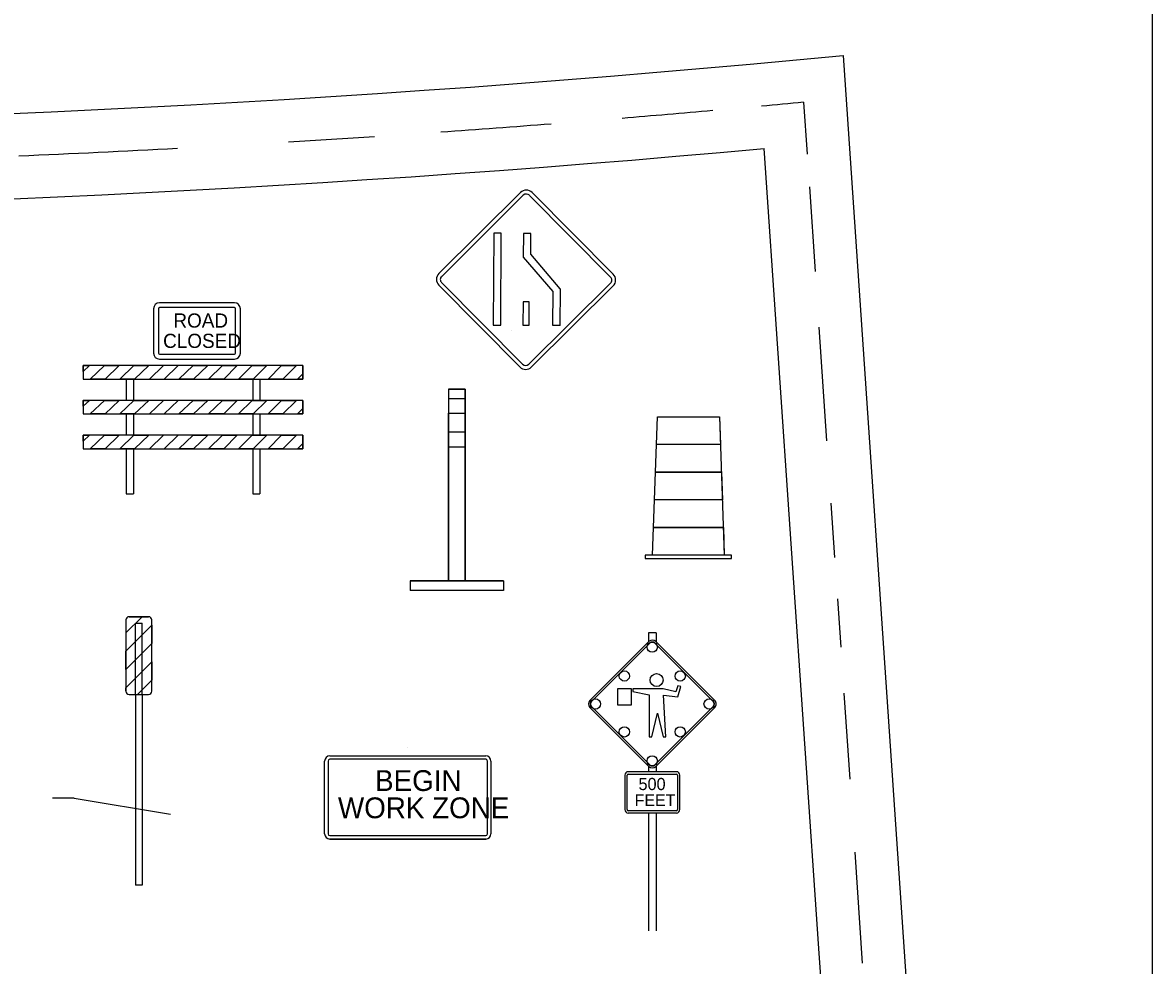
# Model space of a CAD drawing. Extents: x 49991.4 to 50021, y 49987.6 to 50011.4.
# Drawn here: x 50005.965 to 50008.615, y 50005.86 to 50008.071 of the extents above; entities that cross this region are included whole.
import ezdxf

# ---------------------------------------------------------------- set-up
doc = ezdxf.new("R2010")
doc.units = 0
for name, color, linetype in [('Level 1', 7, 'Continuous'), ('Level 2', 7, 'Continuous'), ('Level 25', 7, 'Continuous'), ('Level 4', 7, 'Continuous'), ('Level 7', 7, 'Continuous')]:
    doc.layers.add(name, color=color, linetype=linetype)

msp = doc.modelspace()

# ---------------------------------------------------------------- linework, layer by layer
at = {"layer": 'Level 1'}
for p, q in [((50007.8891, 50007.9941), (50008.1425, 50004.2775)), ((50007.7964, 50007.8845), (50007.8047, 50007.7625)), ((50007.7035, 50007.7757), (50007.8315, 50005.8993)), ((50007.8099, 50007.686), (50007.8234, 50007.4875)), ((50007.8323, 50007.3567), (50007.8505, 50007.0904)), ((50006.9633, 50007.2113), (50006.9633, 50006.7613)), ((50006.9633, 50007.2113), (50006.9633, 50006.7613)), ((50007.0027, 50007.2113), (50007.0027, 50006.7613)), ((50007.0027, 50006.7613), (50007.0027, 50007.2113)), ((50006.9633, 50006.7613), (50006.9633, 50007.1551)), ((50006.9633, 50007.0763), (50007.0027, 50007.0763)), ((50006.9633, 50006.7613), (50006.9633, 50007.0763)), ((50007.6015, 50007.0813), (50007.4511, 50007.0813)), ((50007.6015, 50007.0813), (50007.4511, 50007.0813)), ((50007.4466, 50006.9517), (50007.4488, 50007.0165)), ((50007.6037, 50007.0165), (50007.4488, 50007.0165)), ((50007.4488, 50007.0165), (50007.6037, 50007.0165)), ((50007.6037, 50007.0165), (50007.606, 50006.9517)), ((50007.606, 50006.9517), (50007.4466, 50006.9517)), ((50007.606, 50006.9517), (50007.4466, 50006.9517)), ((50007.8605, 50006.9435), (50007.8692, 50006.816)), ((50007.6083, 50006.8869), (50007.4443, 50006.8869)), ((50007.6083, 50006.8869), (50007.4482, 50006.8869)), ((50007.4482, 50006.8869), (50007.6083, 50006.8869)), ((50007.0927, 50006.7613), (50006.8733, 50006.7613)), ((50006.8733, 50006.7613), (50006.8733, 50006.7388)), ((50006.8733, 50006.7613), (50007.0927, 50006.7613)), ((50007.0927, 50006.7613), (50007.0927, 50006.7388)), ((50007.0927, 50006.7388), (50006.8733, 50006.7388)), ((50007.8758, 50006.7198), (50007.8835, 50006.6061)), ((50006.2448, 50006.6775), (50006.2068, 50006.6395)), ((50006.26, 50006.6775), (50006.2448, 50006.6775)), ((50007.4324, 50006.6398), (50007.4324, 50006.6183)), ((50007.4506, 50006.6398), (50007.4324, 50006.6398)), ((50007.4506, 50006.6398), (50007.4506, 50006.6183)), ((50007.4342, 50006.62), (50007.295, 50006.4809)), ((50007.4367, 50006.6162), (50007.2984, 50006.4777)), ((50007.5848, 50006.4777), (50007.4464, 50006.6162)), ((50007.5881, 50006.4809), (50007.4496, 50006.6193)), ((50007.3604, 50006.4701), (50007.3604, 50006.5088)), ((50007.3604, 50006.5088), (50007.392, 50006.5088)), ((50007.392, 50006.5088), (50007.392, 50006.4701)), ((50007.4668, 50006.5086), (50007.3956, 50006.5086)), ((50007.3956, 50006.5086), (50007.3956, 50006.5022)), ((50007.4967, 50006.5017), (50007.4668, 50006.5086)), ((50007.5011, 50006.5154), (50007.4967, 50006.5017)), ((50007.5086, 50006.5135), (50007.5011, 50006.5154)), ((50007.5017, 50006.4898), (50007.5086, 50006.5135)), ((50006.2291, 50006.4952), (50006.2291, 50006.2283)), ((50006.2453, 50006.4952), (50006.2453, 50006.2255)), ((50007.3956, 50006.5022), (50007.4342, 50006.4946)), ((50007.4342, 50006.4946), (50007.4342, 50006.396)), ((50007.4732, 50006.396), (50007.4681, 50006.4936)), ((50007.4681, 50006.4936), (50007.5017, 50006.4898)), ((50007.8909, 50006.4985), (50007.9046, 50006.2964)), ((50007.295, 50006.4648), (50007.4335, 50006.3264)), ((50007.2984, 50006.468), (50007.4367, 50006.3296)), ((50007.392, 50006.4701), (50007.3604, 50006.4701)), ((50007.4464, 50006.3296), (50007.5848, 50006.468)), ((50007.4496, 50006.3264), (50007.5881, 50006.4648)), ((50007.4405, 50006.396), (50007.4537, 50006.4515)), ((50007.4537, 50006.4515), (50007.4669, 50006.396)), ((50007.4342, 50006.396), (50007.4405, 50006.396)), ((50007.4669, 50006.396), (50007.4732, 50006.396)), ((50006.6851, 50006.3514), (50007.0509, 50006.3514)), ((50006.8681, 50006.3707), (50006.8681, 50006.3707)), ((50006.8681, 50006.3707), (50006.8681, 50006.3707)), ((50006.8681, 50006.3707), (50006.8681, 50006.3707)), ((50006.8681, 50006.3707), (50006.8681, 50006.3707)), ((50006.8681, 50006.3707), (50006.8681, 50006.3707)), ((50006.8681, 50006.3707), (50006.8681, 50006.3707)), ((50006.6728, 50006.1683), (50006.6728, 50006.3389)), ((50006.681, 50006.3389), (50006.681, 50006.1683)), ((50007.0509, 50006.3431), (50006.6851, 50006.3431)), ((50007.055, 50006.1683), (50007.055, 50006.3389)), ((50007.0631, 50006.3389), (50007.0631, 50006.1683)), ((50007.4324, 50006.3274), (50007.4324, 50006.3139)), ((50007.4506, 50006.3274), (50007.4506, 50006.3139)), ((50006.0853, 50006.2522), (50006.0345, 50006.2522)), ((50006.0853, 50006.2522), (50006.3116, 50006.2145)), ((50007.4324, 50006.2172), (50007.4324, 50005.9408)), ((50007.4506, 50006.2172), (50007.4506, 50005.9408)), ((50006.6851, 50006.1643), (50007.0509, 50006.1643)), ((50006.6851, 50006.1561), (50007.0509, 50006.1561)), ((50007.0509, 50006.1561), (50006.6851, 50006.1561)), ((50007.9163, 50006.1256), (50007.934, 50005.8651)), ((50007.8315, 50005.8993), (50007.9298, 50004.4565))]:
    msp.add_line(p, q, dxfattribs=at)
for points in [[(50008.6146, 50011.2628), (50000.3356, 50011.2628), (50000.3356, 50000.0624), (50008.6146, 50000.0624)], [(50007.6105, 50006.8221), (50007.442, 50006.8221), (50007.4534, 50007.1461), (50007.5992, 50007.1461)], [(50007.6083, 50006.8869), (50007.6105, 50006.8221), (50007.442, 50006.8221), (50007.4443, 50006.8869), (50007.6044, 50006.8869)], [(50007.425, 50006.814), (50007.6275, 50006.814), (50007.6275, 50006.8221), (50007.425, 50006.8221)]]:
    msp.add_lwpolyline(points, close=True, dxfattribs=at)
for points in [[(50007.4511, 50007.0813), (50007.4534, 50007.1461), (50007.5992, 50007.1461), (50007.6015, 50007.0813)], [(50006.2068, 50006.6699), (50006.2068, 50006.5028)], [(50006.2068, 50006.6699), (50006.2068, 50006.5028)], [(50006.2144, 50006.6775), (50006.26, 50006.6775)], [(50006.26, 50006.6775), (50006.2144, 50006.6775)], [(50006.2676, 50006.5028), (50006.2676, 50006.6699)], [(50007.501, 50006.5153), (50007.5011, 50006.5154)], [(50006.2144, 50006.4952), (50006.26, 50006.4952)], [(50007.5015, 50006.4899), (50007.5018, 50006.4902)], [(50007.3919, 50006.4701), (50007.392, 50006.4703)]]:
    msp.add_lwpolyline(points, dxfattribs=at)
for centre in [(50007.4415, 50006.6062), (50007.376, 50006.5384), (50007.5071, 50006.5384), (50007.3084, 50006.4728), (50007.5748, 50006.4728), (50007.376, 50006.4073), (50007.5071, 50006.4073), (50007.4415, 50006.3396)]:
    msp.add_circle(centre, 0.012, dxfattribs=at)
for centre, radius, start, end in [((50004.3941, 50043.9715), 36.1468, 264.4363, 275.54852), ((50004.3941, 50043.9715), 36.2468, 275.22979, 275.38583), ((50004.3941, 50043.9715), 36.2468, 274.71135, 275.04859), ((50004.3941, 50043.9715), 36.2468, 274.03687, 274.44663), ((50004.3941, 50043.9715), 36.2468, 273.47079, 273.79018), ((50004.3941, 50043.9715), 36.3468, 264.75129, 275.22467), ((50004.3941, 50043.9715), 36.2468, 272.4697, 273.05829), ((50006.2144, 50006.6699), 0.00759, 90, 180), ((50006.2144, 50006.6699), 0.00759, 90, 180), ((50006.26, 50006.6699), 0.00759, 0, 90), ((50006.2144, 50006.5028), 0.00759, 180, 270), ((50006.26, 50006.5028), 0.00759, 270, 360), ((50006.6852, 50006.339), 0.0123, 90, 180), ((50007.0509, 50006.339), 0.0123, 0, 90), ((50006.6852, 50006.339), 0.00406, 90, 180), ((50007.0509, 50006.339), 0.00406, 0, 90), ((50006.6852, 50006.1683), 0.0123, 180, 270), ((50006.6852, 50006.1683), 0.00406, 180, 270), ((50007.0509, 50006.1683), 0.0123, 270, 360), ((50007.0509, 50006.1683), 0.00406, 270, 360)]:
    msp.add_arc(centre, radius, start, end, dxfattribs=at)
for centre, major_axis, start_param, end_param in [((50007.4416, 50006.6113), (0, 0.0114), 5.497787, 6.983728), ((50007.4415, 50006.6113), (0, 0.00683), 5.497787, 7.068583), ((50007.3031, 50006.4729), (0, 0.0114), 0.785398, 2.356194), ((50007.58, 50006.4729), (0, 0.0114), 3.926991, 5.497791), ((50007.3032, 50006.4728), (0, 0.00683), 0.785398, 2.356194), ((50007.58, 50006.4728), (0, 0.00683), 3.926991, 5.497791), ((50007.4416, 50006.3345), (0, -0.0114), 5.497787, 7.068576), ((50007.4415, 50006.3344), (0, -0.00683), 5.497787, 7.068576)]:
    msp.add_ellipse(centre, major_axis=major_axis, ratio=0.999981, start_param=start_param, end_param=end_param, dxfattribs=at)
msp.add_ellipse((50007.4517, 50006.5289), major_axis=(0, 0.0152), ratio=0.999981, dxfattribs=at)
at = {"layer": 'Level 2'}
for p, q in [((50006.9633, 50007.2113), (50007.0027, 50007.2113)), ((50007.0027, 50007.2113), (50006.9633, 50007.2113)), ((50006.9633, 50007.2113), (50006.9633, 50006.7613)), ((50006.9633, 50007.2113), (50007.0027, 50007.2113)), ((50006.9633, 50007.2113), (50006.9633, 50006.7613)), ((50007.0027, 50007.2113), (50007.0027, 50006.7613)), ((50007.0027, 50007.2113), (50007.0027, 50006.7613)), ((50007.0027, 50007.1888), (50006.9633, 50007.1888)), ((50007.0027, 50006.7613), (50007.0027, 50007.1888)), ((50006.9633, 50007.1551), (50007.0027, 50007.1551)), ((50006.9633, 50006.7613), (50006.9633, 50007.1551)), ((50007.0027, 50007.1101), (50006.9633, 50007.1101)), ((50006.2068, 50006.5965), (50006.2676, 50006.6573)), ((50006.2676, 50006.6573), (50006.2676, 50006.6143)), ((50006.2676, 50006.6143), (50006.2068, 50006.5536)), ((50006.2068, 50006.5536), (50006.2068, 50006.5965)), ((50006.2068, 50006.5106), (50006.2676, 50006.5714)), ((50006.2676, 50006.5714), (50006.2676, 50006.5284)), ((50006.2068, 50006.5028), (50006.2068, 50006.5106)), ((50006.2676, 50006.5284), (50006.2344, 50006.4952))]:
    msp.add_line(p, q, dxfattribs=at)
msp.add_lwpolyline([(50006.2144, 50006.4952), (50006.26, 50006.4952)], dxfattribs=at)
msp.add_arc((50006.2144, 50006.5028), 0.00759, 180, 270, dxfattribs=at)
at = {"layer": 'Level 25'}
for p, q in [((50006.9409, 50007.4822), (50007.1327, 50007.6723)), ((50007.139, 50007.666), (50006.9475, 50007.4758)), ((50007.139, 50007.666), (50007.139, 50007.666)), ((50007.3436, 50007.4742), (50007.1535, 50007.6658)), ((50007.16, 50007.6722), (50007.3501, 50007.4806)), ((50007.0695, 50007.5768), (50007.0685, 50007.3614)), ((50007.0872, 50007.5768), (50007.0695, 50007.5768)), ((50007.0864, 50007.3614), (50007.0872, 50007.5768)), ((50007.1392, 50007.5765), (50007.139, 50007.5208)), ((50007.157, 50007.5765), (50007.1391, 50007.5766)), ((50007.1569, 50007.5274), (50007.157, 50007.5765)), ((50007.1389, 50007.5209), (50007.2079, 50007.4401)), ((50007.2258, 50007.4467), (50007.1568, 50007.5275)), ((50006.9474, 50007.4615), (50007.1374, 50007.2696)), ((50007.131, 50007.2634), (50006.9409, 50007.455)), ((50007.1519, 50007.2696), (50007.3436, 50007.4598)), ((50007.35, 50007.4533), (50007.1582, 50007.2632)), ((50007.2079, 50007.4401), (50007.2077, 50007.361)), ((50007.2255, 50007.3608), (50007.2259, 50007.4465)), ((50007.1385, 50007.4161), (50007.1382, 50007.3612)), ((50007.1528, 50007.416), (50007.1385, 50007.416)), ((50007.1526, 50007.3612), (50007.1528, 50007.416)), ((50007.0685, 50007.3614), (50007.0864, 50007.3614)), ((50007.1382, 50007.3613), (50007.1525, 50007.3613)), ((50007.2076, 50007.361), (50007.2254, 50007.361)), ((50007.377, 50006.3059), (50007.377, 50006.2252)), ((50007.3824, 50006.2252), (50007.3824, 50006.3059)), ((50007.498, 50006.3139), (50007.3851, 50006.3139)), ((50007.3851, 50006.3085), (50007.498, 50006.3085)), ((50007.5007, 50006.3059), (50007.5007, 50006.2252)), ((50007.5061, 50006.2252), (50007.5061, 50006.3059)), ((50007.498, 50006.2225), (50007.3851, 50006.2225)), ((50007.3851, 50006.2172), (50007.498, 50006.2172))]:
    msp.add_line(p, q, dxfattribs=at)
msp.add_lwpolyline([(50007.1106, 50007.348), (50007.1107, 50007.3481)], dxfattribs=at)
for centre, radius, start, end in [((50007.1462, 50007.6587), 0.0193, 44.7658, 134.7656), ((50007.1462, 50007.6587), 0.0102, 44.7658, 134.7656), ((50006.9545, 50007.4686), 0.0193, 134.7656, 224.7658), ((50006.9545, 50007.4686), 0.0102, 134.7656, 224.7658), ((50007.3363, 50007.467), 0.0102, 314.7656, 44.7658), ((50007.3363, 50007.467), 0.0193, 314.7656, 44.7658), ((50007.1446, 50007.2769), 0.0193, 224.7658, 314.7656), ((50007.1446, 50007.2769), 0.0102, 224.7658, 314.7656), ((50007.3851, 50006.3059), 0.00806, 90, 180), ((50007.3851, 50006.3059), 0.00269, 90, 180), ((50007.498, 50006.3059), 0.00806, 0, 90), ((50007.498, 50006.3059), 0.00269, 0, 90), ((50007.3851, 50006.2252), 0.00806, 180, 270), ((50007.3851, 50006.2252), 0.00269, 180, 270), ((50007.498, 50006.2252), 0.00269, 270, 360), ((50007.498, 50006.2252), 0.00806, 270, 360)]:
    msp.add_arc(centre, radius, start, end, dxfattribs=at)
at = {"layer": 'Level 4'}
for p, q in [((50006.2291, 50006.6623), (50006.2453, 50006.6623)), ((50006.2291, 50006.4952), (50006.2291, 50006.6623)), ((50006.2453, 50006.4952), (50006.2453, 50006.6623)), ((50006.2291, 50006.2283), (50006.2291, 50006.0477)), ((50006.2453, 50006.2255), (50006.2453, 50006.0477)), ((50006.2453, 50006.0477), (50006.2291, 50006.0477))]:
    msp.add_line(p, q, dxfattribs=at)
at = {"layer": 'Level 7'}
for p, q in [((50006.4616, 50007.4136), (50006.2855, 50007.4136)), ((50006.2717, 50007.3999), (50006.2717, 50007.2955)), ((50006.283, 50007.3999), (50006.283, 50007.2955)), ((50006.4616, 50007.4024), (50006.2855, 50007.4024)), ((50006.464, 50007.2955), (50006.464, 50007.3999)), ((50006.4753, 50007.2955), (50006.4753, 50007.3999)), ((50006.2855, 50007.293), (50006.4616, 50007.293)), ((50006.2855, 50007.2818), (50006.4616, 50007.2818)), ((50006.1066, 50007.2667), (50006.1066, 50007.2349)), ((50006.1066, 50007.2529), (50006.1066, 50007.2667)), ((50006.1066, 50007.2667), (50006.1217, 50007.2667)), ((50006.1217, 50007.2667), (50006.1066, 50007.2529)), ((50006.6221, 50007.2667), (50006.1066, 50007.2667)), ((50006.1232, 50007.2349), (50006.1565, 50007.2667)), ((50006.1565, 50007.2667), (50006.1911, 50007.2667)), ((50006.1911, 50007.2667), (50006.1579, 50007.2349)), ((50006.1925, 50007.2349), (50006.2257, 50007.2667)), ((50006.2257, 50007.2667), (50006.2603, 50007.2667)), ((50006.2603, 50007.2667), (50006.2271, 50007.2349)), ((50006.295, 50007.2667), (50006.2618, 50007.2349)), ((50006.3296, 50007.2667), (50006.295, 50007.2667)), ((50006.2965, 50007.2349), (50006.3296, 50007.2667)), ((50006.3311, 50007.2349), (50006.3643, 50007.2667)), ((50006.3643, 50007.2667), (50006.3989, 50007.2667)), ((50006.3989, 50007.2667), (50006.3657, 50007.2349)), ((50006.4003, 50007.2349), (50006.4336, 50007.2667)), ((50006.4336, 50007.2667), (50006.4682, 50007.2667)), ((50006.4682, 50007.2667), (50006.4363, 50007.2349)), ((50006.4709, 50007.2349), (50006.5029, 50007.2667)), ((50006.5029, 50007.2667), (50006.5374, 50007.2667)), ((50006.5374, 50007.2667), (50006.5057, 50007.2349)), ((50006.5402, 50007.2349), (50006.5721, 50007.2667)), ((50006.5721, 50007.2667), (50006.6067, 50007.2667)), ((50006.6067, 50007.2667), (50006.5749, 50007.2349)), ((50006.6221, 50007.2667), (50006.6221, 50007.2349)), ((50006.6221, 50007.2349), (50006.6221, 50007.2667)), ((50006.1066, 50007.2349), (50006.6221, 50007.2349)), ((50006.1579, 50007.2349), (50006.1232, 50007.2349)), ((50006.2271, 50007.2349), (50006.1925, 50007.2349)), ((50006.2078, 50007.2349), (50006.2078, 50007.1851)), ((50006.2243, 50007.2349), (50006.2243, 50007.1865)), ((50006.2618, 50007.2349), (50006.2965, 50007.2349)), ((50006.3643, 50007.2349), (50006.3311, 50007.2349)), ((50006.3657, 50007.2349), (50006.3643, 50007.2349)), ((50006.4363, 50007.2349), (50006.4003, 50007.2349)), ((50006.5057, 50007.2349), (50006.4709, 50007.2349)), ((50006.5042, 50007.2349), (50006.5042, 50007.1865)), ((50006.5207, 50007.2349), (50006.5207, 50007.1865)), ((50006.5749, 50007.2349), (50006.5402, 50007.2349)), ((50006.6095, 50007.2349), (50006.6221, 50007.2475)), ((50006.6221, 50007.2349), (50006.6095, 50007.2349)), ((50006.6221, 50007.2475), (50006.6221, 50007.2349)), ((50006.1066, 50007.1851), (50006.1066, 50007.1532)), ((50006.1066, 50007.1712), (50006.1066, 50007.185)), ((50006.1066, 50007.185), (50006.1217, 50007.185)), ((50006.1217, 50007.185), (50006.1066, 50007.1712)), ((50006.6221, 50007.185), (50006.1066, 50007.185)), ((50006.1232, 50007.1532), (50006.1565, 50007.185)), ((50006.1565, 50007.185), (50006.1911, 50007.185)), ((50006.1911, 50007.185), (50006.1579, 50007.1532)), ((50006.1925, 50007.1532), (50006.2257, 50007.185)), ((50006.2257, 50007.185), (50006.2603, 50007.185)), ((50006.2603, 50007.185), (50006.2271, 50007.1532)), ((50006.295, 50007.185), (50006.2618, 50007.1532)), ((50006.3296, 50007.185), (50006.295, 50007.185)), ((50006.2965, 50007.1532), (50006.3296, 50007.185)), ((50006.3311, 50007.1532), (50006.3643, 50007.185)), ((50006.3643, 50007.185), (50006.3989, 50007.185)), ((50006.3989, 50007.185), (50006.3657, 50007.1532)), ((50006.4003, 50007.1532), (50006.4336, 50007.185)), ((50006.4336, 50007.185), (50006.4682, 50007.185)), ((50006.4682, 50007.185), (50006.4363, 50007.1532)), ((50006.4709, 50007.1532), (50006.5029, 50007.185)), ((50006.5029, 50007.185), (50006.5374, 50007.185)), ((50006.5374, 50007.185), (50006.5057, 50007.1532)), ((50006.5402, 50007.1532), (50006.5721, 50007.185)), ((50006.5721, 50007.185), (50006.6067, 50007.185)), ((50006.6067, 50007.185), (50006.5749, 50007.1532)), ((50006.6221, 50007.185), (50006.6221, 50007.1532)), ((50006.6221, 50007.1532), (50006.6221, 50007.185)), ((50006.1066, 50007.1532), (50006.6221, 50007.1532)), ((50006.1579, 50007.1532), (50006.1232, 50007.1532)), ((50006.2271, 50007.1532), (50006.1925, 50007.1532)), ((50006.2078, 50007.1532), (50006.2078, 50007.1032)), ((50006.2243, 50007.1532), (50006.2243, 50007.1032)), ((50006.2618, 50007.1532), (50006.2965, 50007.1532)), ((50006.3643, 50007.1532), (50006.3311, 50007.1532)), ((50006.3657, 50007.1532), (50006.3643, 50007.1532)), ((50006.4363, 50007.1532), (50006.4003, 50007.1532)), ((50006.5057, 50007.1532), (50006.4709, 50007.1532)), ((50006.5042, 50007.1532), (50006.5042, 50007.1032)), ((50006.5207, 50007.1532), (50006.5207, 50007.1032)), ((50006.5749, 50007.1532), (50006.5402, 50007.1532)), ((50006.6095, 50007.1532), (50006.6221, 50007.1657)), ((50006.6221, 50007.1532), (50006.6095, 50007.1532)), ((50006.6221, 50007.1657), (50006.6221, 50007.1532)), ((50006.1066, 50007.0894), (50006.1066, 50007.1032)), ((50006.1066, 50007.1032), (50006.1217, 50007.1032)), ((50006.1217, 50007.1032), (50006.1066, 50007.0894)), ((50006.6221, 50007.1032), (50006.1066, 50007.1032)), ((50006.1066, 50007.1032), (50006.1066, 50007.0714)), ((50006.1232, 50007.0714), (50006.1565, 50007.1032)), ((50006.1565, 50007.1032), (50006.1911, 50007.1032)), ((50006.1911, 50007.1032), (50006.1579, 50007.0714)), ((50006.1925, 50007.0714), (50006.2257, 50007.1032)), ((50006.2257, 50007.1032), (50006.2603, 50007.1032)), ((50006.2603, 50007.1032), (50006.2271, 50007.0714)), ((50006.295, 50007.1032), (50006.2618, 50007.0714)), ((50006.3296, 50007.1032), (50006.295, 50007.1032)), ((50006.2965, 50007.0714), (50006.3296, 50007.1032)), ((50006.3311, 50007.0714), (50006.3643, 50007.1032)), ((50006.3643, 50007.1032), (50006.3989, 50007.1032)), ((50006.3989, 50007.1032), (50006.3657, 50007.0714)), ((50006.4003, 50007.0714), (50006.4336, 50007.1032)), ((50006.4336, 50007.1032), (50006.4682, 50007.1032)), ((50006.4682, 50007.1032), (50006.4363, 50007.0714)), ((50006.4709, 50007.0714), (50006.5029, 50007.1032)), ((50006.5029, 50007.1032), (50006.5374, 50007.1032)), ((50006.5374, 50007.1032), (50006.5057, 50007.0714)), ((50006.5402, 50007.0714), (50006.5721, 50007.1032)), ((50006.5721, 50007.1032), (50006.6067, 50007.1032)), ((50006.6067, 50007.1032), (50006.5749, 50007.0714)), ((50006.6221, 50007.1032), (50006.6221, 50007.0714)), ((50006.6221, 50007.0714), (50006.6221, 50007.1032)), ((50006.1066, 50007.0714), (50006.6221, 50007.0714)), ((50006.1579, 50007.0714), (50006.1232, 50007.0714)), ((50006.2271, 50007.0714), (50006.1925, 50007.0714)), ((50006.2078, 50007.0714), (50006.2078, 50006.9661)), ((50006.2243, 50007.0714), (50006.2243, 50006.9661)), ((50006.2618, 50007.0714), (50006.2965, 50007.0714)), ((50006.3643, 50007.0714), (50006.3311, 50007.0714)), ((50006.3657, 50007.0714), (50006.3643, 50007.0714)), ((50006.4363, 50007.0714), (50006.4003, 50007.0714)), ((50006.5057, 50007.0714), (50006.4709, 50007.0714)), ((50006.5042, 50007.0714), (50006.5042, 50006.9661)), ((50006.5207, 50007.0714), (50006.5207, 50006.9661)), ((50006.5749, 50007.0714), (50006.5402, 50007.0714)), ((50006.6095, 50007.0714), (50006.6221, 50007.084)), ((50006.6221, 50007.0714), (50006.6095, 50007.0714)), ((50006.6221, 50007.084), (50006.6221, 50007.0714)), ((50006.2078, 50006.9661), (50006.2243, 50006.9661)), ((50006.5042, 50006.9661), (50006.5207, 50006.9661))]:
    msp.add_line(p, q, dxfattribs=at)
for points in [[(50006.1066, 50007.2667), (50006.1066, 50007.2667)], [(50006.1066, 50007.1851), (50006.1066, 50007.1851)]]:
    msp.add_lwpolyline(points, dxfattribs=at)
for centre, radius, start, end in [((50006.2855, 50007.3999), 0.0137, 90, 180), ((50006.4616, 50007.3999), 0.0137, 360, 90), ((50006.2855, 50007.3999), 0.00249, 90, 180), ((50006.4616, 50007.3999), 0.00249, 360, 90), ((50006.2855, 50007.2955), 0.0137, 180, 270), ((50006.2855, 50007.2955), 0.00249, 180, 270), ((50006.4616, 50007.2955), 0.00249, 270, 360), ((50006.4616, 50007.2955), 0.0137, 270, 360)]:
    msp.add_arc(centre, radius, start, end, dxfattribs=at)

# ---------------------------------------------------------------- texts
at = {"layer": 'Level 1'}
for s, p in [('BEGIN', (50006.7913, 50006.2688)), ('WORK ZONE', (50006.7042, 50006.2049))]:
    msp.add_text(s, height=0.04876, dxfattribs=at).set_placement(p)
at = {"layer": 'Level 25'}
for s, height, p in [('500', 0.02849, (50007.4092, 50006.2709)), ('FEET', 0.02796, (50007.4002, 50006.2333))]:
    msp.add_text(s, height=height, dxfattribs=at).set_placement(p)
at = {"layer": 'Level 7'}
for s, p in [('ROAD', (50006.3182, 50007.3556)), ('CLOSED', (50006.2941, 50007.3079))]:
    msp.add_text(s, height=0.03321, rotation=360, dxfattribs=at).set_placement(p)

doc.saveas('drawing.dxf')
